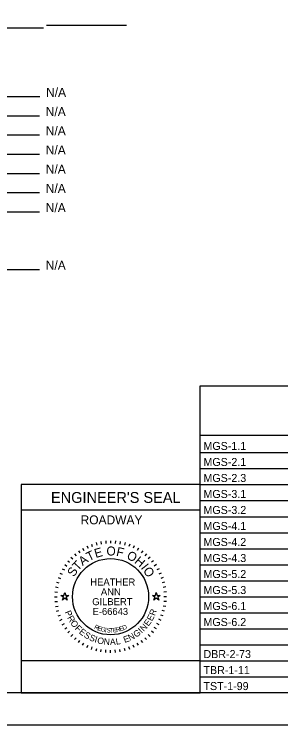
# Model space of a CAD drawing. Extents: x 0 to 34, y 0 to 22.
# Drawn here: x 7.24 to 11.41, y 0 to 11.1 of the extents above; entities that cross this region are included whole.
import ezdxf

# ---------------------------------------------------------------- set-up
doc = ezdxf.new("R2010")
doc.units = 0
for name, color, linetype in [('Default', 7, 'Continuous'), ('SH_Border', 7, 'Continuous'), ('SH_Cut_Line', 7, 'Continuous'), ('SH_Data', 7, 'Continuous'), ('SH_Text', 7, 'Continuous')]:
    doc.layers.add(name, color=color, linetype=linetype)

msp = doc.modelspace()

# ---------------------------------------------------------------- linework, layer by layer
at = {"layer": 'Default'}
for points in [[(7.974, 2.02), (8.021, 2.02), (8.035, 2.065), (8.049, 2.02), (8.096, 2.02), (8.058, 1.992), (8.073, 1.948), (8.035, 1.975), (7.997, 1.948), (8.012, 1.992)], [(9.404, 2.02), (9.451, 2.02), (9.465, 2.065), (9.479, 2.02), (9.526, 2.02), (9.488, 1.992), (9.503, 1.948), (9.465, 1.975), (9.427, 1.948), (9.442, 1.992)]]:
    msp.add_lwpolyline(points, close=True, dxfattribs=at)
at = {"layer": 'SH_Border'}
msp.add_lwpolyline([(1.5, 21.5), (33.5, 21.5), (33.5, 0.5), (1.5, 0.5)], close=True, dxfattribs=at)
at = {"layer": 'SH_Cut_Line'}
msp.add_lwpolyline([(0, 0), (34, 0), (34, 22), (0, 22)], close=True, dxfattribs=at)
at = {"layer": 'SH_Data'}
for p, q in [((7.7, 10.877), (3.347, 10.877)), ((9, 10.922), (7.75, 10.922)), ((7.642, 9.806), (3.871, 9.806)), ((7.637, 9.506), (4.189, 9.506)), ((7.637, 9.206), (4.872, 9.206)), ((7.637, 8.906), (4.604, 8.906)), ((7.637, 8.606), (4.189, 8.606)), ((7.637, 8.306), (3.346, 8.306)), ((7.637, 8.006), (3.242, 8.006)), ((7.637, 7.106), (3.267, 7.106)), ((10.15, 5.292), (23.6, 5.292)), ((10.15, 0.5), (10.15, 5.292)), ((10.15, 4.521), (23.6, 4.521)), ((10.15, 4.25), (23.6, 4.25)), ((10.15, 4), (23.6, 4)), ((10.15, 3.75), (7.35, 3.75)), ((7.35, 3.75), (7.35, 0.5)), ((10.15, 3.75), (23.6, 3.75)), ((10.15, 0.5), (10.15, 3.75)), ((10.15, 3.5), (23.6, 3.5)), ((10.15, 3.35), (7.35, 3.35)), ((10.15, 3.25), (23.6, 3.25)), ((10.15, 3), (23.6, 3)), ((8.38, 2.793), (8.397, 2.757)), ((8.451, 2.822), (8.464, 2.785)), ((8.524, 2.845), (8.534, 2.807)), ((8.598, 2.862), (8.605, 2.822)), ((8.674, 2.872), (8.677, 2.832)), ((8.75, 2.875), (8.75, 2.835)), ((8.826, 2.872), (8.823, 2.832)), ((8.902, 2.862), (8.895, 2.822)), ((8.976, 2.845), (8.966, 2.807)), ((9.049, 2.822), (9.036, 2.785)), ((9.12, 2.793), (9.103, 2.757)), ((8.188, 2.67), (8.213, 2.64)), ((8.248, 2.717), (8.271, 2.684)), ((8.313, 2.758), (8.333, 2.723)), ((9.187, 2.758), (9.167, 2.723)), ((9.252, 2.717), (9.229, 2.684)), ((9.312, 2.67), (9.287, 2.64)), ((10.15, 2.75), (23.6, 2.75)), ((8.08, 2.562), (8.11, 2.537)), ((8.131, 2.619), (8.16, 2.59)), ((9.369, 2.619), (9.34, 2.59)), ((9.42, 2.562), (9.39, 2.537)), ((8.033, 2.502), (8.066, 2.479)), ((9.467, 2.502), (9.434, 2.479)), ((10.15, 2.5), (23.6, 2.5)), ((7.957, 2.37), (7.993, 2.353)), ((7.992, 2.438), (8.027, 2.418)), ((9.508, 2.438), (9.473, 2.418)), ((9.543, 2.37), (9.507, 2.353)), ((7.905, 2.226), (7.943, 2.216)), ((7.928, 2.299), (7.965, 2.286)), ((9.572, 2.299), (9.535, 2.286)), ((9.595, 2.226), (9.557, 2.216)), ((10.15, 2.25), (23.6, 2.25)), ((7.888, 2.152), (7.928, 2.145)), ((9.612, 2.152), (9.572, 2.145)), ((7.875, 2), (7.915, 2)), ((7.878, 2.076), (7.918, 2.073)), ((9.622, 2.076), (9.582, 2.073)), ((9.625, 2), (9.585, 2)), ((10.15, 2), (23.6, 2)), ((7.878, 1.924), (7.918, 1.927)), ((9.622, 1.924), (9.582, 1.927)), ((7.888, 1.848), (7.928, 1.855)), ((7.905, 1.774), (7.943, 1.784)), ((9.595, 1.774), (9.557, 1.784)), ((9.612, 1.848), (9.572, 1.855)), ((7.928, 1.701), (7.965, 1.714)), ((9.572, 1.701), (9.535, 1.714)), ((10.15, 1.75), (23.6, 1.75)), ((7.957, 1.63), (7.993, 1.647)), ((7.992, 1.563), (8.027, 1.583)), ((9.508, 1.563), (9.473, 1.583)), ((9.543, 1.63), (9.507, 1.647)), ((8.033, 1.498), (8.066, 1.521)), ((8.08, 1.438), (8.11, 1.463)), ((9.42, 1.438), (9.39, 1.463)), ((9.467, 1.498), (9.434, 1.521)), ((10.15, 1.5), (23.6, 1.5)), ((8.131, 1.381), (8.16, 1.41)), ((8.188, 1.33), (8.213, 1.36)), ((9.312, 1.33), (9.287, 1.36)), ((9.369, 1.381), (9.34, 1.41)), ((8.248, 1.283), (8.271, 1.316)), ((8.313, 1.242), (8.333, 1.277)), ((8.38, 1.207), (8.397, 1.243)), ((9.12, 1.207), (9.103, 1.243)), ((9.187, 1.242), (9.167, 1.277)), ((9.252, 1.283), (9.229, 1.316)), ((10.15, 1.25), (23.6, 1.25)), ((8.451, 1.178), (8.464, 1.215)), ((8.524, 1.155), (8.534, 1.193)), ((8.598, 1.138), (8.605, 1.178)), ((8.674, 1.128), (8.677, 1.168)), ((8.75, 1.125), (8.75, 1.165)), ((8.826, 1.128), (8.823, 1.168)), ((8.902, 1.138), (8.895, 1.178)), ((8.976, 1.155), (8.966, 1.193)), ((9.049, 1.178), (9.036, 1.215)), ((10.15, 1), (23.6, 1)), ((10.15, 0.75), (23.6, 0.75)), ((10.15, 0.5), (7.35, 0.5))]:
    msp.add_line(p, q, dxfattribs=at)
msp.add_lwpolyline([(10.15, 0.5), (10.15, 1), (7.35, 1), (7.35, 0.5)], close=True, dxfattribs=at)
msp.add_circle((8.75, 2), 0.595, dxfattribs=at)

# ---------------------------------------------------------------- texts
at = {"layer": 'Default'}
for s, p in [('MGS-1.1', (10.202, 4.292)), ('MGS-2.1', (10.202, 4.042)), ('MGS-2.3', (10.202, 3.792)), ('MGS-3.1', (10.202, 3.542)), ('MGS-3.2', (10.202, 3.292)), ('MGS-4.1', (10.202, 3.042)), ('MGS-4.2', (10.202, 2.792)), ('MGS-4.3', (10.202, 2.542)), ('MGS-5.2', (10.202, 2.292)), ('MGS-5.3', (10.202, 2.042)), ('MGS-6.1', (10.202, 1.792)), ('MGS-6.2', (10.202, 1.542)), ('DBR-2-73', (10.202, 1.042)), ('TBR-1-11', (10.202, 0.792)), ('TST-1-99', (10.202, 0.542))]:
    msp.add_text(s, height=0.125, dxfattribs=at).set_placement(p)
at = {"layer": 'SH_Data'}
for s, height, p in [("ENGINEER'S SEAL", 0.17, (7.818, 3.465)), ('ROADWAY', 0.14, (8.281, 3.13)), ('HEATHER', 0.11, (8.433, 2.175)), ('ANN', 0.11, (8.599, 2.022)), ('GILBERT', 0.11, (8.463, 1.868)), ('E-66643', 0.11, (8.468, 1.715))]:
    msp.add_text(s, height=height, dxfattribs=at).set_placement(p)
for s, height, rotation, p in [('O', 0.14, 359.7812, (8.685, 2.644)), ('F', 0.14, 347.4362, (8.831, 2.642)), ('T', 0.14, 25.7167, (8.412, 2.552)), ('E', 0.14, 15.7571, (8.518, 2.604)), ('O', 0.14, 332.2586, (8.99, 2.602)), ('T', 0.14, 46.4344, (8.238, 2.396)), ('A', 0.14, 36.4747, (8.313, 2.478)), ('H', 0.14, 319.9136, (9.113, 2.536)), ('S', 0.14, 57.1924, (8.178, 2.301)), ('I', 0.14, 308.367, (9.216, 2.448)), ('O', 0.14, 303.1491, (9.252, 2.409)), ('P', 0.1, 291.494, (8.032, 1.762)), ('R', 0.1, 69.2322, (9.442, 1.695)), ('R', 0.1, 298.7311, (8.069, 1.672)), ('E', 0.1, 61.9951, (9.398, 1.61)), ('O', 0.1, 306.4666, (8.115, 1.588)), ('F', 0.1, 314.7068, (8.184, 1.498)), ('R', 0.07, 334.487, (8.487, 1.505)), ('D', 0.07, 23.3052, (8.951, 1.477)), ('N', 0.1, 47.0224, (9.27, 1.451)), ('E', 0.1, 54.758, (9.343, 1.531)), ('E', 0.1, 321.4393, (8.248, 1.435)), ('S', 0.1, 328.6764, (8.324, 1.375)), ('E', 0.07, 341.04, (8.541, 1.48)), ('G', 0.07, 347.4752, (8.591, 1.462)), ('I', 0.07, 353.7858, (8.659, 1.447)), ('S', 0.07, 356.8926, (8.686, 1.443)), ('T', 0.07, 3.0061, (8.736, 1.439)), ('E', 0.07, 6.0117, (8.789, 1.441)), ('R', 0.07, 11.9184, (8.842, 1.447)), ('E', 0.07, 17.6836, (8.9, 1.46)), ('G', 0.1, 35.0469, (9.148, 1.357)), ('I', 0.1, 43.287, (9.237, 1.421)), ('S', 0.1, 335.9134, (8.406, 1.327)), ('I', 0.1, 343.1505, (8.491, 1.29)), ('O', 0.1, 346.8859, (8.534, 1.275)), ('N', 0.1, 355.1261, (8.639, 1.252)), ('A', 0.1, 2.8617, (8.742, 1.244)), ('L', 0.1, 10.0987, (8.839, 1.249)), ('E', 0.1, 20.0742, (8.971, 1.277)), ('N', 0.1, 27.3113, (9.054, 1.308))]:
    msp.add_text(s, height=height, rotation=rotation, dxfattribs=at).set_placement(p)
at = {"layer": 'SH_Text'}
for p in [(7.742, 9.806), (7.737, 9.506), (7.737, 9.206), (7.737, 8.906), (7.737, 8.606), (7.737, 8.306), (7.737, 8.006), (7.737, 7.106)]:
    msp.add_text('N/A', height=0.14, dxfattribs=at).set_placement(p)

doc.saveas('drawing.dxf')
